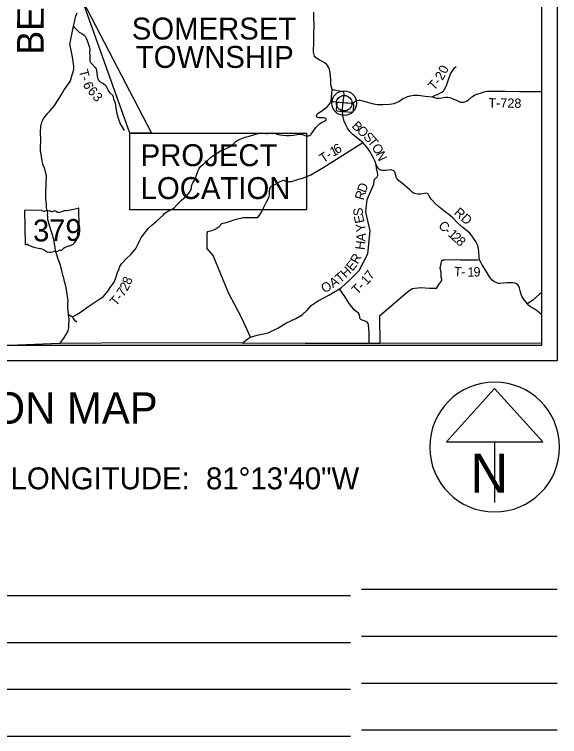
# Model space of a CAD drawing. Extents: x 0 to 2329303, y 0 to 694397.
# Drawn here: x 5.532 to 9.015, y 11.6 to 16.215 of the extents above; entities that cross this region are included whole.
import ezdxf

# ---------------------------------------------------------------- set-up
doc = ezdxf.new("R2010")
doc.units = 0
for name, color, linetype in [('GM_X_City_Street', 7, 'Continuous'), ('GM_X_County', 7, 'Continuous'), ('GM_X_County_Road', 7, 'Continuous'), ('GM_X_County_Road_Text', 7, 'Continuous'), ('GM_X_State_Route', 7, 'Continuous'), ('GM_X_State_Shield', 7, 'Continuous'), ('GM_X_Township', 7, 'Continuous'), ('GM_X_Township_Road', 7, 'Continuous'), ('GM_X_Township_Road_Text', 7, 'Continuous'), ('GM_X_Township_ROW', 7, 'Continuous'), ('GM_X_Township_Subdivision', 7, 'Continuous'), ('GM_X_Township_Text', 7, 'Continuous'), ('GM_X_Unincorporated', 7, 'Continuous'), ('SH_Data', 7, 'Continuous'), ('SH_Masking', 7, 'Continuous')]:
    doc.layers.add(name, color=color, linetype=linetype)

msp = doc.modelspace()

# ---------------------------------------------------------------- linework, layer by layer
at = {"layer": 'GM_X_City_Street'}
msp.add_line((9, 11.64), (7.75, 11.64), dxfattribs=at)
at = {"layer": 'GM_X_County_Road'}
msp.add_line((9, 12.24), (7.75, 12.24), dxfattribs=at)
for points in [[(7.6327, 15.5581), (7.6306, 15.5682), (7.6282, 15.595), (7.6287, 15.6141), (7.632, 15.6529), (7.6385, 15.7069), (7.6376, 15.7158), (7.6317, 15.721), (7.6094, 15.7245), (7.5857, 15.7276), (7.5754, 15.73), (7.5625, 15.7353), (7.5573, 15.7497), (7.5544, 15.7619), (7.5531, 15.7973), (7.5488, 15.843), (7.5457, 15.8618), (7.5397, 15.8767), (7.533, 15.8876), (7.5254, 15.8964), (7.5064, 15.9094), (7.4801, 15.9244), (7.4684, 15.9308), (7.4599, 15.9364), (7.4536, 15.9421), (7.4487, 15.9489), (7.4463, 15.9567), (7.4444, 15.9656), (7.4435, 15.9739), (7.4459, 16.0427), (7.4459, 16.088), (7.4467, 16.1433), (7.446, 16.1983), (7.4453, 16.2296)], [(7.6406, 15.5274), (7.6397, 15.5295), (7.6346, 15.5489), (7.6327, 15.5581)], [(8.9, 14.2969), (8.8919, 14.303), (8.8734, 14.3187), (8.8478, 14.3357), (8.8294, 14.3472), (8.8207, 14.3531), (8.8169, 14.3575), (8.8104, 14.3655), (8.7838, 14.3969), (8.775, 14.4106), (8.7687, 14.4253), (8.7636, 14.4474), (8.7591, 14.4659), (8.7542, 14.4786), (8.7483, 14.4871), (8.7395, 14.4934), (8.7318, 14.4964), (8.7168, 14.4993), (8.6778, 14.499), (8.6359, 14.4947), (8.6244, 14.4942), (8.6132, 14.4987), (8.5952, 14.5076), (8.5844, 14.5156), (8.574, 14.5285), (8.5674, 14.5384), (8.5465, 14.5749), (8.5207, 14.6153), (8.5131, 14.6271), (8.5037, 14.6465), (8.5012, 14.6671), (8.4997, 14.6979), (8.4978, 14.7161), (8.4949, 14.7291), (8.488, 14.7474), (8.4778, 14.7666), (8.4567, 14.7985), (8.442, 14.8159), (8.4293, 14.8284), (8.3991, 14.8518), (8.3636, 14.8831), (8.3321, 14.914), (8.3067, 14.936), (8.2851, 14.9525), (8.2422, 14.9883), (8.2203, 15.0075), (8.2006, 15.027), (8.1942, 15.0352), (8.1829, 15.0565), (8.178, 15.0641), (8.173, 15.0686), (8.1681, 15.0708), (8.163, 15.0717), (8.1525, 15.0711), (8.1287, 15.0671), (8.1089, 15.066), (8.0966, 15.0674), (8.0851, 15.0708), (8.0726, 15.0788), (8.0576, 15.093), (8.0132, 15.132), (7.9888, 15.1513), (7.9793, 15.1617), (7.9737, 15.1693), (7.9701, 15.1792), (7.9673, 15.1914), (7.9643, 15.2031), (7.9599, 15.2118), (7.9567, 15.2154), (7.9515, 15.2177), (7.9431, 15.2199), (7.9359, 15.2207), (7.9039, 15.2177), (7.8811, 15.2181), (7.872, 15.2195), (7.8652, 15.2231), (7.8589, 15.2281), (7.8531, 15.2357), (7.8442, 15.2531), (7.8365, 15.2743), (7.8239, 15.2994), (7.8123, 15.323), (7.8057, 15.336), (7.7995, 15.346), (7.7929, 15.3548), (7.7728, 15.3793), (7.7584, 15.3956), (7.6973, 15.4444), (7.6754, 15.4656), (7.6609, 15.4879), (7.6468, 15.5129), (7.6406, 15.5274)]]:
    msp.add_lwpolyline(points, dxfattribs=at)
at = {"layer": 'GM_X_State_Route'}
msp.add_line((9, 12.54), (7.75, 12.54), dxfattribs=at)
msp.add_lwpolyline([(5.8223, 14.1123), (5.8475, 14.1466), (5.8698, 14.1794), (5.8756, 14.1951), (5.8792, 14.2115), (5.8805, 14.2318), (5.8813, 14.2669), (5.8787, 14.2966), (5.8751, 14.3213), (5.8739, 14.3436), (5.8736, 14.3604), (5.8745, 14.37), (5.8753, 14.3839), (5.8745, 14.3938), (5.8737, 14.4012), (5.8723, 14.4119), (5.868, 14.4423), (5.866, 14.4538), (5.8605, 14.4787), (5.8531, 14.5081), (5.847, 14.5294), (5.8422, 14.549), (5.8353, 14.5779), (5.8264, 14.6108), (5.8205, 14.6299), (5.8122, 14.6511), (5.8031, 14.6789), (5.7956, 14.7062), (5.7921, 14.724), (5.7832, 14.7766), (5.7807, 14.7893), (5.7774, 14.8003), (5.767, 14.8315), (5.7561, 14.8653), (5.7463, 14.9036), (5.7448, 14.9204), (5.7446, 14.9328), (5.7453, 14.9446), (5.7427, 14.9541), (5.7398, 14.9686), (5.7372, 14.9801), (5.7364, 15.0029), (5.7352, 15.0178), (5.7331, 15.0395), (5.7323, 15.0836), (5.7341, 15.1246), (5.7356, 15.1541), (5.7364, 15.1636), (5.737, 15.1749), (5.7365, 15.1823), (5.736, 15.188), (5.7333, 15.2015), (5.7293, 15.2171), (5.7271, 15.2253), (5.7229, 15.2364), (5.7183, 15.2472), (5.7141, 15.2584), (5.7109, 15.2698), (5.7092, 15.2794), (5.7046, 15.3063), (5.7001, 15.3347), (5.6994, 15.3408), (5.6983, 15.3501), (5.6979, 15.3582), (5.6986, 15.374), (5.7005, 15.3975), (5.7012, 15.4116), (5.7009, 15.4289), (5.6995, 15.4446), (5.6994, 15.4736), (5.7002, 15.4887), (5.7012, 15.5011), (5.7029, 15.5095), (5.7044, 15.5166), (5.71, 15.5321), (5.721, 15.5527), (5.7373, 15.5738), (5.7447, 15.5839), (5.7534, 15.5928), (5.7702, 15.6103), (5.7805, 15.6221), (5.7905, 15.6359), (5.8036, 15.6562), (5.8327, 15.7024), (5.8509, 15.7334), (5.8879, 15.7868), (5.8924, 15.7988), (5.8992, 15.8231), (5.9066, 15.8478), (5.9121, 15.8664), (5.9123, 15.8762), (5.9115, 15.8853), (5.9099, 15.8972), (5.905, 15.9301), (5.896, 15.9744), (5.8879, 16.0156), (5.8871, 16.0235), (5.8882, 16.0316), (5.8904, 16.0422), (5.8953, 16.0666), (5.9009, 16.0963), (5.9095, 16.1387), (5.9153, 16.1643), (5.9203, 16.1857), (5.9253, 16.2032), (5.9332, 16.2243)], dxfattribs=at)
at = {"layer": 'GM_X_State_Shield'}
for p, q in [((5.5969, 14.959), (5.6005, 14.7477)), ((5.7022, 14.9644), (5.6003, 14.9627)), ((5.9466, 14.8632), (5.9448, 14.9737)), ((5.9466, 14.8632), (5.9466, 14.8632))]:
    msp.add_line(p, q, dxfattribs=at)
for centre, major_axis, start_param, end_param in [((5.6009, 14.9595), (0.00403, 0.00007), 1.712693, 3.28349), ((5.7261, 14.9893), (0.0391, 0.0007), 4.042523, 4.731795), ((5.7414, 14.8464), (0.1404, 0.0024), 1.404758, 1.657858), ((5.7714, 14.9635), (0.0113, 0.0002), 3.836095, 5.185415), ((5.7883, 14.9393), (0.0235, 0.0004), 0.950623, 2.079405), ((5.818, 14.9733), (0.0282, 0.0005), 4.081561, 5.145723), ((5.8691, 14.9026), (0.0742, 0.0012), 1.699011, 2.107814), ((5.8161, 15.2544), (0.369, 0.0062), 4.814394, 5.042369), ((5.9409, 14.9741), (0.00387, 0.00006), 6.141152, 7.989035), ((5.9459, 14.855), (0.006, 0.0001), 1.883978, 3.671073), ((5.9425, 14.8627), (0.00415, 0.00007), 5.05454, 6.418171), ((5.8444, 14.8011), (0.0923, 0.0015), 5.101752, 6.440018), ((5.9613, 14.8171), (0.0262, 0.0004), 2.387724, 3.262537), ((5.908, 14.8404), (0.036, 0.0006), 5.934695, 6.695948), ((5.6045, 14.7473), (0.00407, 0.00007), 3.00124, 4.508301), ((5.6048, 14.7689), (0.031, 0.0005), 4.665946, 4.897461), ((5.6117, 14.7357), (0.0112, 0.0002), 0.519207, 1.627899), ((5.7498, 14.9279), (0.2665, 0.0045), 4.195997, 4.488961), ((5.8851, 14.6931), (0.0506, 0.0008), 1.647645, 2.488434), ((5.6749, 14.654), (0.0834, 0.0014), 0.823519, 1.323587), ((5.7637, 14.7372), (0.0529, 0.0009), 4.026481, 4.996735), ((5.7955, 14.6646), (0.0435, 0.0007), 1.495662, 1.94098), ((5.7984, 14.7219), (0.0282, 0.0005), 4.691044, 5.507374), ((5.8243, 14.7019), (0.00794, 0.00013), 1.147584, 2.315152), ((5.8204, 14.7309), (0.0298, 0.0005), 4.937069, 5.64225)]:
    msp.add_ellipse(centre, major_axis=major_axis, ratio=0.8, start_param=start_param, end_param=end_param, dxfattribs=at)
at = {"layer": 'GM_X_Township'}
msp.add_lwpolyline([(8.9, 14.1135), (7.8667, 14.1128), (7.7976, 14.1127), (7.39, 14.1123), (6.9864, 14.1137), (6.3526, 14.1158), (5.8223, 14.1123), (5.5, 14.1)], dxfattribs=at)
at = {"layer": 'GM_X_Township_Road'}
msp.add_line((9, 11.94), (7.75, 11.94), dxfattribs=at)
for points in [[(5.9095, 16.1387), (5.915, 16.1338), (5.9208, 16.1271), (5.9278, 16.1197), (5.9348, 16.1123), (5.9415, 16.1058), (5.9483, 16.1), (5.9546, 16.0963), (5.9628, 16.0926), (5.9696, 16.0895), (5.9765, 16.0839), (5.9833, 16.0764), (5.9901, 16.0637), (5.9978, 16.0472), (6.0055, 16.0222), (6.0109, 16.004), (6.0132, 15.9915), (6.0125, 15.9713), (6.0145, 15.9513), (6.0142, 15.9307), (6.0145, 15.9155), (6.0182, 15.9086), (6.0295, 15.8975), (6.0477, 15.8759), (6.054, 15.8666), (6.0574, 15.8577), (6.0614, 15.8208), (6.0633, 15.8072), (6.0691, 15.7936), (6.0825, 15.782), (6.1018, 15.7729), (6.1156, 15.7608), (6.1257, 15.7431), (6.1337, 15.7249), (6.1424, 15.7131), (6.1601, 15.6964), (6.1652, 15.6761), (6.1754, 15.6494), (6.1807, 15.6158), (6.1869, 15.5807), (6.1948, 15.5518), (6.2086, 15.5151), (6.2331, 15.4723)], [(8.2022, 15.6881), (8.2114, 15.6952), (8.2347, 15.7041), (8.2623, 15.7185), (8.2728, 15.725), (8.2806, 15.7374), (8.2922, 15.7601), (8.3059, 15.7982), (8.3174, 15.8353), (8.3431, 15.8736), (8.3552, 15.8821)], [(7.6629, 15.6495), (7.6844, 15.6476), (7.6953, 15.6503), (7.7057, 15.6559), (7.7131, 15.6607), (7.7222, 15.6648), (7.7311, 15.667), (7.741, 15.6667), (7.7584, 15.662), (7.7951, 15.6521), (7.8267, 15.644), (7.8525, 15.6383), (7.889, 15.6395), (7.9284, 15.642), (7.959, 15.6465), (7.9871, 15.6591), (8.0121, 15.6746), (8.0401, 15.6886), (8.0607, 15.6946), (8.0839, 15.698), (8.1108, 15.6985), (8.1564, 15.6922), (8.1797, 15.6902), (8.2022, 15.6881)], [(8.2022, 15.6881), (8.2142, 15.6839), (8.2296, 15.6802), (8.2434, 15.6797), (8.2638, 15.6824), (8.285, 15.6855), (8.2993, 15.6866), (8.3149, 15.6843), (8.3327, 15.6763), (8.356, 15.6662), (8.3727, 15.6586), (8.3828, 15.6548), (8.3912, 15.6532), (8.4003, 15.6534), (8.4102, 15.6557), (8.4209, 15.6604), (8.4305, 15.6673), (8.4553, 15.6891), (8.4718, 15.6988), (8.4874, 15.7049), (8.5088, 15.7123), (8.5396, 15.7221), (8.5516, 15.7237), (8.606, 15.7248), (8.6676, 15.7239), (8.7598, 15.7229), (8.8447, 15.7232), (8.9, 15.7226)], [(5.8787, 14.2966), (5.9031, 14.2812), (5.9316, 14.2971), (5.9664, 14.3209), (6.0021, 14.3461), (6.033, 14.3684), (6.0722, 14.393), (6.0892, 14.4039), (6.0999, 14.4107), (6.1103, 14.422), (6.1315, 14.4489), (6.1444, 14.4688), (6.1574, 14.4863), (6.169, 14.5042), (6.176, 14.5217), (6.1821, 14.5387), (6.1918, 14.565), (6.2004, 14.5881), (6.2044, 14.6006), (6.209, 14.6104), (6.2163, 14.6201), (6.2472, 14.653), (6.2775, 14.6836), (6.3077, 14.7185), (6.3209, 14.7436), (6.3338, 14.7732), (6.3422, 14.7894), (6.3913, 14.8511), (6.4112, 14.8682), (6.4386, 14.8919), (6.4815, 14.9324), (6.491, 14.9421), (6.5026, 14.9515), (6.5444, 14.9734), (6.5521, 14.979), (6.5751, 15.002), (6.5921, 15.0195), (6.6001, 15.028), (6.6142, 15.0413), (6.6287, 15.051), (6.6389, 15.0616), (6.6484, 15.0746), (6.6549, 15.0832), (6.6595, 15.0931), (6.6626, 15.1037), (6.6646, 15.1147), (6.6686, 15.1299), (6.6727, 15.1395), (6.6801, 15.1512), (6.6872, 15.1633), (6.6943, 15.1817), (6.7065, 15.2167), (6.7125, 15.2307), (6.7237, 15.2445), (6.7409, 15.2589), (6.7818, 15.2981), (6.806, 15.3151), (6.8537, 15.3445), (6.881, 15.3565), (6.9039, 15.3658), (6.9162, 15.3729), (6.9274, 15.3827), (6.9377, 15.3948), (6.9473, 15.4021), (6.9595, 15.4117), (6.975, 15.4185), (7.0074, 15.4304), (7.0317, 15.4375), (7.0678, 15.4473), (7.0893, 15.4543), (7.0999, 15.4568), (7.1126, 15.4572), (7.1263, 15.4558), (7.1387, 15.4536), (7.1489, 15.4532), (7.1688, 15.4567), (7.1812, 15.4572), (7.2001, 15.4535), (7.2175, 15.4479), (7.2446, 15.4431), (7.2686, 15.4412), (7.2893, 15.4409), (7.316, 15.4433), (7.3382, 15.4481), (7.3501, 15.45), (7.3615, 15.4492), (7.3711, 15.4476), (7.3825, 15.4435), (7.3948, 15.4391), (7.4027, 15.4383), (7.4118, 15.4391), (7.4165, 15.4402), (7.4211, 15.4424), (7.4257, 15.4452), (7.4289, 15.4487), (7.4388, 15.4649), (7.4589, 15.4916), (7.4805, 15.5166), (7.4976, 15.5268), (7.5098, 15.5314), (7.5218, 15.5381), (7.5237, 15.5416), (7.5238, 15.5472), (7.5211, 15.5501), (7.5161, 15.5524), (7.5078, 15.5533), (7.478, 15.5544), (7.4702, 15.5561), (7.4664, 15.5592), (7.4635, 15.5636), (7.4628, 15.5695), (7.4646, 15.5761), (7.4723, 15.5841), (7.4969, 15.5986), (7.5295, 15.6251), (7.5417, 15.6364), (7.55, 15.648), (7.5552, 15.66), (7.5603, 15.6591)], [(7.5603, 15.6591), (7.5656, 15.6582), (7.5924, 15.6559), (7.6012, 15.6551)], [(7.6012, 15.6551), (7.6078, 15.6545), (7.632, 15.6529)], [(7.632, 15.6529), (7.65, 15.6504), (7.6606, 15.6497), (7.6629, 15.6495)], [(7.2872, 15.1461), (7.306, 15.1478), (7.326, 15.1548), (7.3722, 15.1694), (7.4117, 15.1824), (7.4252, 15.1891), (7.5097, 15.2392), (7.6481, 15.3252), (7.7584, 15.3956)], [(7.7822, 14.9936), (7.7859, 15.0324), (7.8289, 15.1291), (7.83, 15.1541), (7.8314, 15.1577), (7.8494, 15.176), (7.852, 15.1803), (7.8534, 15.1861), (7.8532, 15.1926), (7.8509, 15.2049), (7.8452, 15.2326), (7.8442, 15.2531)], [(6.9864, 14.1137), (7.0313, 14.149), (7.0396, 14.1515), (7.0821, 14.1645), (7.1523, 14.1796), (7.2151, 14.2096), (7.2653, 14.2424), (7.3305, 14.2725), (7.3698, 14.2949), (7.4043, 14.3279), (7.427, 14.3553), (7.4737, 14.3855), (7.5411, 14.4202), (7.6084, 14.4619), (7.6216, 14.4702), (7.6748, 14.5195), (7.734, 14.5792), (7.7891, 14.6856), (7.8052, 14.8328), (7.7782, 14.9515), (7.7822, 14.9936)], [(8.5037, 14.6465), (8.4883, 14.6441), (8.4491, 14.6446), (8.4247, 14.6451), (8.4008, 14.6434), (8.3828, 14.6444), (8.3508, 14.6457), (8.2809, 14.6452), (8.2701, 14.6444), (8.2665, 14.6432), (8.2634, 14.6419), (8.2605, 14.6381), (8.2584, 14.6335), (8.2504, 14.5927), (8.2515, 14.5866), (8.255, 14.5771), (8.2559, 14.5659), (8.2559, 14.5648)], [(8.9, 14.4366), (8.8866, 14.4277), (8.8432, 14.3882), (8.8104, 14.3655)], [(5.93, 14.2485), (5.923, 14.2551), (5.908, 14.2734), (5.9031, 14.2812)]]:
    msp.add_lwpolyline(points, dxfattribs=at)
at = {"layer": 'GM_X_Township_ROW'}
for points in [[(7.0396, 14.1515), (6.9843, 14.2745), (6.8998, 14.4352), (6.8023, 14.6738), (6.7629, 14.7181), (6.7628, 14.7711), (6.7636, 14.8049), (6.7664, 14.8267), (6.7934, 14.8345), (6.8152, 14.8421), (6.8407, 14.8591), (6.8568, 14.8794), (6.8855, 14.8857), (6.9105, 14.8939), (6.9486, 14.9073), (6.9933, 14.9175), (7.0883, 14.918), (7.1086, 14.9479), (7.1236, 14.9788), (7.1432, 15.0182), (7.1579, 15.0443), (7.1604, 15.0504), (7.1626, 15.0644), (7.1628, 15.0844), (7.164, 15.0992), (7.1653, 15.1073), (7.168, 15.1124), (7.1724, 15.1164), (7.1968, 15.1285), (7.226, 15.1453), (7.2445, 15.1541), (7.2487, 15.1549), (7.2549, 15.1545), (7.2605, 15.1523), (7.2723, 15.1475), (7.284, 15.1458), (7.2872, 15.1461)], [(8.2559, 14.5648), (8.2556, 14.5524), (8.2566, 14.5368), (8.2596, 14.5235), (8.261, 14.5147), (8.2408, 14.4878), (8.226, 14.4631), (8.1838, 14.4643), (8.127, 14.4674), (8.0742, 14.4602), (8.0417, 14.4381), (7.8639, 14.2863), (7.8668, 14.1128)], [(7.7976, 14.1127), (7.7983, 14.1784), (7.7947, 14.2312), (7.7923, 14.2393), (7.7873, 14.2464), (7.7817, 14.2509), (7.7737, 14.2542), (7.7542, 14.2607), (7.7448, 14.2656), (7.7404, 14.2702), (7.7384, 14.2745), (7.738, 14.2804), (7.7372, 14.2944), (7.7354, 14.2998), (7.7295, 14.306), (7.7043, 14.3246), (7.671, 14.367), (7.6435, 14.4119), (7.6084, 14.4619)]]:
    msp.add_lwpolyline(points, dxfattribs=at)
at = {"layer": 'GM_X_Township_Subdivision'}
for points in [[(7.5552, 15.66), (7.5625, 15.7353)], [(7.5924, 15.6559), (7.5913, 15.6439), (7.5877, 15.607), (7.5886, 15.6023), (7.5914, 15.5992), (7.6282, 15.595), (7.6943, 15.5906), (7.6978, 15.6006), (7.7014, 15.6363), (7.6994, 15.6437), (7.6953, 15.6503)]]:
    msp.add_lwpolyline(points, dxfattribs=at)
at = {"layer": 'GM_X_Unincorporated'}
for radius in [0.0786, 0.0498]:
    msp.add_circle((7.6388, 15.6475), radius, dxfattribs=at)
at = {"layer": 'SH_Data'}
for p, q in [((8.6, 13.8238), (8.2924, 13.4825)), ((8.9076, 13.4825), (8.6, 13.8238)), ((8.2924, 13.4825), (8.9076, 13.4825)), ((8.6, 13.4825), (8.6, 13.0958)), ((7.68, 12.5), (3.65, 12.5)), ((7.68, 12.2), (3.75, 12.2)), ((7.68, 11.9), (3.98, 11.9)), ((7.68, 11.6), (3.62, 11.6))]:
    msp.add_line(p, q, dxfattribs=at)
for points in [[(2, 21), (9, 21), (9, 14), (2, 14)], [(2.1, 20.9), (8.9, 20.9), (8.9, 14.1), (2.1, 14.1)], [(6.4087, 15.4552), (6.2687, 15.4552), (5.9675, 16.303)], [(6.2687, 15.4552), (7.3987, 15.4552), (7.3987, 14.9652), (6.2687, 14.9652)]]:
    msp.add_lwpolyline(points, close=True, dxfattribs=at)
msp.add_arc((8.6, 13.45), 0.4148, 90, 89.9835, dxfattribs=at)
at = {"layer": 'SH_Masking'}
msp.add_lwpolyline([(6.2687, 15.4552), (7.3987, 15.4552), (7.3987, 14.9652), (6.2687, 14.9652)], close=True, dxfattribs=at)

# ---------------------------------------------------------------- texts
at = {"layer": 'GM_X_County'}
msp.add_text('BELMONT COUNTY', height=0.17, rotation=89.7416, dxfattribs=at).set_placement((5.7189, 15.9576))
at = {"layer": 'GM_X_County_Road_Text'}
for s, rotation, p in [('B', 316.4408, (7.683, 15.4968)), ('O', 316.2507, (7.7152, 15.4671)), ('S', 313.8442, (7.7575, 15.428)), ('T', 309.3345, (7.7852, 15.4002)), ('O', 298.9808, (7.8126, 15.3684)), ('N', 294.794, (7.8384, 15.3236)), ('RD', 318.1239, (8.3365, 14.9419)), ('C', 315.9605, (8.236, 14.8595)), ('-', 316.2957, (8.2722, 14.8256)), ('1', 317.4863, (8.2978, 14.804)), ('2', 319.9614, (8.3212, 14.7816)), ('8', 313.9181, (8.3486, 14.7595))]:
    msp.add_text(s, height=0.06, rotation=rotation, dxfattribs=at).set_placement(p)
at = {"layer": 'GM_X_State_Shield'}
msp.add_text('379', height=0.13922, rotation=0.961, dxfattribs=at).set_placement((5.6525, 14.7635))
at = {"layer": 'GM_X_Township_Road_Text'}
for s, rotation, p in [('0', 64.1558, (8.2902, 15.8313)), ('T', 283.9411, (5.9428, 15.855)), ('2', 60.593, (8.2667, 15.7891)), ('6', 289.5294, (5.9696, 15.7722)), ('-', 284.5926, (5.9546, 15.8109)), ('T', 47.5568, (8.2129, 15.7241)), ('-', 50.123, (8.2446, 15.76)), ('6', 313.1419, (5.9961, 15.7203)), ('3', 311.6513, (6.0274, 15.6839)), ('T-728', 359.1784, (8.5607, 15.62)), ('1', 26.6873, (7.5657, 15.3037)), ('6', 29.5294, (7.5916, 15.3205)), ('T', 33.2526, (7.5052, 15.263)), ('-', 33.5131, (7.5425, 15.2884)), ('D', 69.2052, (7.775, 15.0705)), ('R', 73.5501, (7.7622, 15.0241)), ('S', 93.3898, (7.7594, 14.9281)), ('E', 101.7932, (7.769, 14.8866)), ('Y', 97.2737, (7.7775, 14.8293)), ('A', 84.8578, (7.7741, 14.7624)), ('H', 82.9224, (7.7683, 14.7077)), ('R', 60.9347, (7.7258, 14.6153)), ('E', 50.7731, (7.6917, 14.5703)), ('H', 43.7222, (7.6488, 14.5272)), ('7', 54.0947, (7.8124, 14.5152)), ('T', 355.893, (8.3383, 14.543)), ('1', 359.404, (8.4262, 14.5393)), ('9', 1.8347, (8.4659, 14.5396)), ('8', 68.2327, (6.2729, 14.4827)), ('T', 40.8714, (7.6129, 14.495)), ('1', 47.1544, (7.7828, 14.4815)), ('-', 358.3236, (8.3859, 14.5405)), ('2', 62.0325, (6.2533, 14.4433)), ('O', 28.3769, (7.5111, 14.432)), ('A', 32.172, (7.5666, 14.4651)), ('T', 44.0742, (7.7214, 14.4199)), ('7', 55.3442, (6.2289, 14.4059)), ('-', 44.7162, (7.7536, 14.4521)), ('T', 49.1235, (6.1815, 14.3458)), ('-', 53.5433, (6.2134, 14.3842))]:
    msp.add_text(s, height=0.06, rotation=rotation, dxfattribs=at).set_placement(p)
at = {"layer": 'GM_X_Township_Text'}
for s, p in [('SOMERSET', (6.2819, 16.0543)), ('TOWNSHIP', (6.3079, 15.8731))]:
    msp.add_text(s, height=0.14, rotation=0, dxfattribs=at).set_placement(p)
at = {"layer": 'SH_Data'}
for s, height, p in [('PROJECT', 0.14, (6.3387, 15.2452)), ('LOCATION', 0.14, (6.3387, 15.0352)), ('LOCATION MAP', 0.2, (4.4265, 13.6)), ('N', 0.25, (8.4447, 13.1587)), ('LATITUDE:  39°53\'55"N     LONGITUDE:  81°13\'40"W', 0.14, (3.25, 13.18))]:
    msp.add_text(s, height=height, dxfattribs=at).set_placement(p)

doc.saveas('drawing.dxf')
